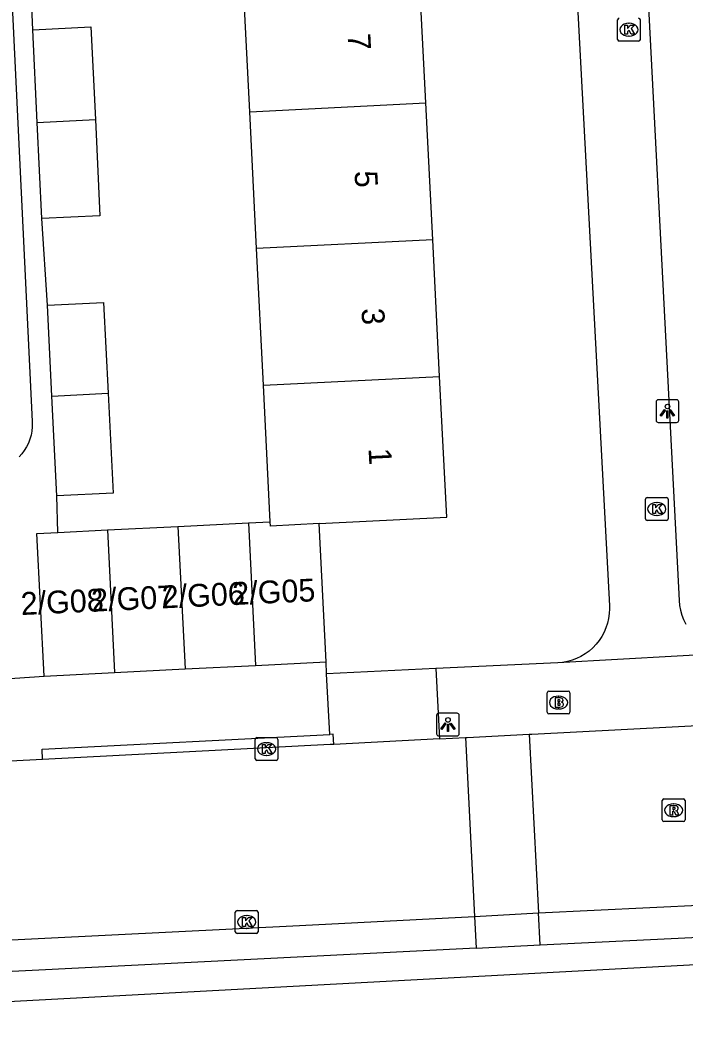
# Model space of a CAD drawing. Extents: x 161084 to 161928, y 385355 to 386522.
# Drawn here: x 161538.55 to 161567.76, y 385444.58 to 385488.38 of the extents above; entities that cross this region are included whole.
import ezdxf

# ---------------------------------------------------------------- set-up
doc = ezdxf.new("R2010")
doc.units = 0
for name, color, linetype in [('IMGEO_Brandkraan', 7, 'Continuous'), ('IMGEO_Kolk', 7, 'Continuous'), ('IMGEO_Lichtpunt', 7, 'Continuous'), ('IMGEO_Pand', 7, 'Continuous'), ('IMGEO_Pand_nummerreeks', 7, 'Continuous'), ('IMGEO_Parkeervlak_open', 7, 'Continuous'), ('IMGEO_Rijbaan_lokaal_open', 7, 'Continuous'), ('IMGEO_Rioolput', 7, 'Continuous'), ('IMGEO_Voetpad_open', 7, 'Continuous')]:
    doc.layers.add(name, color=color, linetype=linetype)

msp = doc.modelspace()

# ---------------------------------------------------------------- linework, layer by layer
at = {"layer": 'IMGEO_Brandkraan'}
for p, q in [((161561.702, 385457.968), (161561.702, 385458.82)), ((161561.777, 385458.894), (161562.629, 385458.894)), ((161562.703, 385458.82), (161562.703, 385457.968)), ((161562.19, 385458.674), (161562.215, 385458.674)), ((161562.629, 385457.894), (161561.777, 385457.894)), ((161562.213, 385458.114), (161562.188, 385458.114))]:
    msp.add_line(p, q, dxfattribs=at)
for points in [[(161561.702, 385457.968), (161561.702, 385458.82)], [(161561.777, 385458.894), (161562.629, 385458.894)], [(161562.703, 385458.82), (161562.703, 385457.968)], [(161562.05, 385458.594), (161562.05, 385458.194), (161562.263, 385458.194)], [(161562.281, 385458.594), (161562.05, 385458.594)], [(161562.229, 385458.513), (161562.175, 385458.513), (161562.175, 385458.437)], [(161562.175, 385458.437), (161562.228, 385458.437)], [(161562.237, 385458.361), (161562.175, 385458.361), (161562.175, 385458.28)], [(161562.175, 385458.28), (161562.237, 385458.28)], [(161562.629, 385457.894), (161561.777, 385457.894)]]:
    msp.add_lwpolyline(points, dxfattribs=at)
for centre, radius, start, end in [((161561.779, 385458.818), 0.0765, 91.552, 178.448), ((161561.779, 385458.818), 0.0765, 91.552, 178.448), ((161562.627, 385458.818), 0.0765, 1.552, 88.448), ((161562.627, 385458.818), 0.0765, 1.552, 88.448), ((161562.23, 385458.475), 0.0379, 267.8285, 90.9355), ((161562.238, 385458.32), 0.0404, 269.8759, 90.5077), ((161562.285, 385458.449), 0.145, 59.4692, 91.5367), ((161562.31, 385458.496), 0.0922, 285.5137, 58.1501), ((161562.315, 385458.304), 0.105, 301.3115, 78.989), ((161561.779, 385457.97), 0.0765, 181.552, 268.448), ((161561.779, 385457.97), 0.0765, 181.552, 268.448), ((161562.269, 385458.445), 0.251, 268.6676, 293.5347), ((161562.627, 385457.97), 0.0765, 271.552, 358.448), ((161562.627, 385457.97), 0.0765, 271.552, 358.448)]:
    msp.add_arc(centre, radius, start, end, dxfattribs=at)
for centre, major_axis, ratio, start_param, end_param in [((161562.189, 385458.394), (-0.387, 0.002), 0.722429, 4.712389, 7.853982), ((161562.214, 385458.394), (-0.39, 0.002), 0.717154, 1.570796, 4.712389)]:
    msp.add_ellipse(centre, major_axis=major_axis, ratio=ratio, start_param=start_param, end_param=end_param, dxfattribs=at)
at = {"layer": 'IMGEO_Kolk'}
for p, q in [((161564.792, 385487.526), (161564.792, 385488.378)), ((161565.28, 385488.232), (161565.305, 385488.232)), ((161565.793, 385488.378), (161565.793, 385487.526)), ((161565.303, 385487.672), (161565.278, 385487.672)), ((161565.719, 385487.452), (161564.867, 385487.452)), ((161566.015, 385466.468), (161566.015, 385467.32)), ((161566.09, 385467.394), (161566.942, 385467.394)), ((161566.503, 385467.174), (161566.528, 385467.174)), ((161567.016, 385467.32), (161567.016, 385466.468)), ((161566.526, 385466.614), (161566.501, 385466.614)), ((161566.942, 385466.394), (161566.09, 385466.394)), ((161548.876, 385455.925), (161548.876, 385456.777)), ((161548.951, 385456.851), (161549.803, 385456.851)), ((161549.364, 385456.631), (161549.389, 385456.631)), ((161549.877, 385456.777), (161549.877, 385455.925)), ((161549.803, 385455.851), (161548.951, 385455.851)), ((161549.387, 385456.071), (161549.362, 385456.071)), ((161548.005, 385448.328), (161548.005, 385449.18)), ((161548.08, 385449.254), (161548.932, 385449.254)), ((161549.006, 385449.18), (161549.006, 385448.328)), ((161548.493, 385449.034), (161548.518, 385449.034)), ((161548.932, 385448.254), (161548.08, 385448.254)), ((161548.516, 385448.474), (161548.491, 385448.474))]:
    msp.add_line(p, q, dxfattribs=at)
for points in [[(161564.792, 385487.526), (161564.792, 385488.378)], [(161565.113, 385488.152), (161565.236, 385488.152), (161565.236, 385488.001), (161565.366, 385488.152), (161565.53, 385488.152), (161565.384, 385488.001), (161565.537, 385487.752), (161565.385, 385487.752), (161565.3, 385487.916), (161565.236, 385487.849), (161565.236, 385487.752), (161565.113, 385487.752), (161565.113, 385488.152)], [(161565.793, 385488.378), (161565.793, 385487.526)], [(161565.719, 385487.452), (161564.867, 385487.452)], [(161566.015, 385466.468), (161566.015, 385467.32)], [(161566.09, 385467.394), (161566.942, 385467.394)], [(161566.336, 385467.094), (161566.459, 385467.094), (161566.459, 385466.943), (161566.589, 385467.094), (161566.753, 385467.094), (161566.607, 385466.943), (161566.76, 385466.694), (161566.608, 385466.694), (161566.523, 385466.858), (161566.459, 385466.791), (161566.459, 385466.694), (161566.336, 385466.694), (161566.336, 385467.094)], [(161567.016, 385467.32), (161567.016, 385466.468)], [(161566.942, 385466.394), (161566.09, 385466.394)], [(161548.876, 385455.925), (161548.876, 385456.777)], [(161548.951, 385456.851), (161549.803, 385456.851)], [(161549.197, 385456.551), (161549.32, 385456.551), (161549.32, 385456.4), (161549.45, 385456.551), (161549.614, 385456.551), (161549.468, 385456.4), (161549.621, 385456.151), (161549.469, 385456.151), (161549.384, 385456.315), (161549.32, 385456.248), (161549.32, 385456.151), (161549.197, 385456.151), (161549.197, 385456.551)], [(161549.877, 385456.777), (161549.877, 385455.925)], [(161549.803, 385455.851), (161548.951, 385455.851)], [(161548.005, 385448.328), (161548.005, 385449.18)], [(161548.08, 385449.254), (161548.932, 385449.254)], [(161549.006, 385449.18), (161549.006, 385448.328)], [(161548.326, 385448.954), (161548.449, 385448.954), (161548.449, 385448.803), (161548.579, 385448.954), (161548.743, 385448.954), (161548.597, 385448.803), (161548.75, 385448.554), (161548.598, 385448.554), (161548.513, 385448.718), (161548.449, 385448.651), (161548.449, 385448.554), (161548.326, 385448.554), (161548.326, 385448.954)], [(161548.932, 385448.254), (161548.08, 385448.254)]]:
    msp.add_lwpolyline(points, dxfattribs=at)
for centre, start, end in [((161564.869, 385488.376), 91.552, 178.448), ((161564.869, 385488.376), 91.552, 178.448), ((161565.717, 385488.376), 1.552, 88.448), ((161565.717, 385488.376), 1.552, 88.448), ((161564.869, 385487.528), 181.552, 268.448), ((161564.869, 385487.528), 181.552, 268.448), ((161565.717, 385487.528), 271.552, 358.448), ((161565.717, 385487.528), 271.552, 358.448), ((161566.092, 385467.318), 91.552, 178.448), ((161566.092, 385467.318), 91.552, 178.448), ((161566.94, 385467.318), 1.552, 88.448), ((161566.94, 385467.318), 1.552, 88.448), ((161566.092, 385466.47), 181.552, 268.448), ((161566.092, 385466.47), 181.552, 268.448), ((161566.94, 385466.47), 271.552, 358.448), ((161566.94, 385466.47), 271.552, 358.448), ((161548.953, 385456.775), 91.552, 178.448), ((161548.953, 385456.775), 91.552, 178.448), ((161549.801, 385456.775), 1.552, 88.448), ((161549.801, 385456.775), 1.552, 88.448), ((161548.953, 385455.927), 181.552, 268.448), ((161548.953, 385455.927), 181.552, 268.448), ((161549.801, 385455.927), 271.552, 358.448), ((161549.801, 385455.927), 271.552, 358.448), ((161548.082, 385449.178), 91.552, 178.448), ((161548.082, 385449.178), 91.552, 178.448), ((161548.93, 385449.178), 1.552, 88.448), ((161548.93, 385449.178), 1.552, 88.448), ((161548.082, 385448.33), 181.552, 268.448), ((161548.082, 385448.33), 181.552, 268.448), ((161548.93, 385448.33), 271.552, 358.448), ((161548.93, 385448.33), 271.552, 358.448)]:
    msp.add_arc(centre, 0.0765, start, end, dxfattribs=at)
for centre, major_axis, ratio, start_param, end_param in [((161565.279, 385487.952), (-0.387, 0.002), 0.722429, 4.712389, 7.853982), ((161565.304, 385487.952), (-0.39, 0.002), 0.717154, 1.570796, 4.712389), ((161566.502, 385466.894), (-0.387, 0.002), 0.722429, 4.712389, 7.853982), ((161566.527, 385466.894), (-0.39, 0.002), 0.717154, 1.570796, 4.712389), ((161549.363, 385456.351), (-0.387, 0.002), 0.722429, 4.712389, 7.853982), ((161549.388, 385456.351), (-0.39, 0.002), 0.717154, 1.570796, 4.712389), ((161548.492, 385448.754), (-0.387, 0.002), 0.722429, 4.712389, 7.853982), ((161548.517, 385448.754), (-0.39, 0.002), 0.717154, 1.570796, 4.712389)]:
    msp.add_ellipse(centre, major_axis=major_axis, ratio=ratio, start_param=start_param, end_param=end_param, dxfattribs=at)
at = {"layer": 'IMGEO_Lichtpunt'}
for p, q in [((161566.484, 385471.597), (161566.484, 385470.79)), ((161566.484, 385471.597), (161566.484, 385470.79)), ((161567.386, 385471.692), (161566.578, 385471.692)), ((161567.386, 385471.692), (161566.578, 385471.692)), ((161567.48, 385470.79), (161567.48, 385471.597)), ((161567.48, 385470.79), (161567.48, 385471.597)), ((161566.578, 385470.696), (161567.386, 385470.696)), ((161566.578, 385470.696), (161567.386, 385470.696)), ((161557.747, 385457.927), (161556.939, 385457.927)), ((161557.747, 385457.927), (161556.939, 385457.927)), ((161556.845, 385457.832), (161556.845, 385457.025)), ((161556.845, 385457.832), (161556.845, 385457.025)), ((161557.841, 385457.025), (161557.841, 385457.832)), ((161557.841, 385457.025), (161557.841, 385457.832)), ((161556.939, 385456.931), (161557.747, 385456.931)), ((161556.939, 385456.931), (161557.747, 385456.931))]:
    msp.add_line(p, q, dxfattribs=at)
for points in [[(161566.858, 385471.261), (161566.897, 385471.233), (161566.709, 385470.971), (161566.671, 385470.998), (161566.858, 385471.261)], [(161566.96, 385471.213), (161567.007, 385471.213), (161567.007, 385470.891), (161566.96, 385470.891), (161566.96, 385471.213)], [(161567.07, 385471.233), (161567.108, 385471.26), (161567.295, 385470.998), (161567.256, 385470.97), (161567.07, 385471.233)], [(161557.219, 385457.496), (161557.258, 385457.468), (161557.07, 385457.206), (161557.032, 385457.233), (161557.219, 385457.496)], [(161557.321, 385457.448), (161557.368, 385457.448), (161557.368, 385457.126), (161557.321, 385457.126), (161557.321, 385457.448)], [(161557.431, 385457.468), (161557.469, 385457.495), (161557.656, 385457.233), (161557.617, 385457.205), (161557.431, 385457.468)]]:
    msp.add_lwpolyline(points, dxfattribs=at)
for centre in [(161566.983, 385471.395), (161557.344, 385457.63)]:
    msp.add_circle(centre, 0.0994, dxfattribs=at)
for centre, start, end in [((161566.578, 385471.597), 90, 180), ((161566.578, 385471.597), 90, 180), ((161567.386, 385471.597), 0, 90), ((161567.386, 385471.597), 0, 90), ((161566.578, 385470.79), 180, 270), ((161566.578, 385470.79), 180, 270), ((161567.386, 385470.79), 270, 0), ((161567.386, 385470.79), 270, 360), ((161556.939, 385457.832), 90, 180), ((161556.939, 385457.832), 90, 180), ((161557.747, 385457.832), 0, 90), ((161557.747, 385457.832), 0, 90), ((161556.939, 385457.025), 180, 270), ((161556.939, 385457.025), 180, 270), ((161557.747, 385457.025), 270, 0), ((161557.747, 385457.025), 270, 360)]:
    msp.add_arc(centre, 0.0946, start, end, dxfattribs=at)
at = {"layer": 'IMGEO_Pand'}
for points in [[(161556.372, 385484.73), (161556.068, 385490.735)], [(161548.639, 385484.34), (161548.353, 385490.088)], [(161539.114, 385487.949), (161541.665, 385488.07), (161541.857, 385483.998)], [(161539.307, 385483.869), (161539.114, 385487.949)], [(161548.639, 385484.34), (161556.372, 385484.73)], [(161556.676, 385478.724), (161556.372, 385484.73)], [(161548.939, 385478.333), (161548.639, 385484.34)], [(161539.307, 385483.869), (161541.857, 385483.998)], [(161539.506, 385479.653), (161539.307, 385483.869)], [(161541.857, 385483.998), (161542.057, 385479.774), (161539.506, 385479.653)], [(161556.676, 385478.724), (161548.939, 385478.333)], [(161556.979, 385472.719), (161556.676, 385478.724)], [(161549.238, 385472.328), (161548.939, 385478.333)], [(161539.754, 385475.844), (161542.217, 385475.966), (161542.415, 385471.983)], [(161539.952, 385471.859), (161539.754, 385475.844)], [(161549.238, 385472.328), (161556.979, 385472.719)], [(161549.537, 385466.337), (161549.238, 385472.328)], [(161551.681, 385466.253), (161557.292, 385466.539), (161556.979, 385472.719)], [(161539.952, 385471.859), (161542.415, 385471.983)], [(161540.17, 385467.472), (161539.952, 385471.859)], [(161542.415, 385471.983), (161542.633, 385467.594), (161540.17, 385467.472)], [(161545.482, 385466.13), (161548.577, 385466.288)], [(161548.577, 385466.288), (161549.537, 385466.337)], [(161548.577, 385466.288), (161548.896, 385460.027)], [(161551.681, 385466.253), (161549.546, 385466.147), (161549.537, 385466.337)], [(161551.99, 385460.184), (161551.681, 385466.253)], [(161539.612, 385459.554), (161539.294, 385465.815), (161540.207, 385465.862)], [(161540.207, 385465.862), (161542.388, 385465.973)], [(161542.388, 385465.973), (161545.482, 385466.13)], [(161542.388, 385465.973), (161542.706, 385459.712)], [(161545.482, 385466.13), (161545.801, 385459.869)], [(161545.801, 385459.869), (161548.896, 385460.027)], [(161548.896, 385460.027), (161551.99, 385460.184)], [(161539.612, 385459.554), (161542.706, 385459.712)], [(161542.706, 385459.712), (161545.801, 385459.869)], [(161575.301, 385447.248), (161530.941, 385444.868), (161530.957, 385444.578)]]:
    msp.add_lwpolyline(points, dxfattribs=at)
at = {"layer": 'IMGEO_Parkeervlak_open'}
for points in [[(161561.395, 385447.744), (161561.322, 385449.16)], [(161558.515, 385448.993), (161558.586, 385447.605)]]:
    msp.add_lwpolyline(points, dxfattribs=at)
at = {"layer": 'IMGEO_Rijbaan_lokaal_open'}
for points in [[(161560.918, 385457), (161561.024, 385457.005), (161583.443, 385458.171)], [(161558.111, 385456.854), (161558.187, 385456.858), (161560.918, 385457)], [(161560.918, 385457), (161561.322, 385449.16)], [(161552.326, 385456.553), (161552.175, 385456.545), (161539.541, 385455.888)], [(161556.969, 385456.794), (161552.326, 385456.553)], [(161556.969, 385456.794), (161558.111, 385456.854)], [(161558.111, 385456.854), (161558.515, 385448.993)], [(161539.541, 385455.888), (161538.131, 385455.814)], [(161561.322, 385449.16), (161568.656, 385449.513), (161574.004, 385449.781)], [(161558.515, 385448.993), (161561.322, 385449.16)], [(161522.558, 385447.214), (161526.215, 385447.371), (161534.038, 385447.759), (161550.827, 385448.607), (161558.515, 385448.993)]]:
    msp.add_lwpolyline(points, dxfattribs=at)
at = {"layer": 'IMGEO_Rioolput'}
for p, q in [((161566.756, 385453.237), (161566.756, 385454.089)), ((161566.831, 385454.163), (161567.683, 385454.163)), ((161567.244, 385453.943), (161567.269, 385453.943)), ((161567.757, 385454.089), (161567.757, 385453.237)), ((161567.683, 385453.163), (161566.831, 385453.163)), ((161567.267, 385453.383), (161567.242, 385453.383))]:
    msp.add_line(p, q, dxfattribs=at)
for points in [[(161566.756, 385453.237), (161566.756, 385454.089)], [(161566.831, 385454.163), (161567.683, 385454.163)], [(161567.757, 385454.089), (161567.757, 385453.237)], [(161567.345, 385453.861), (161567.093, 385453.863), (161567.093, 385453.463)], [(161567.093, 385453.463), (161567.217, 385453.463), (161567.217, 385453.625), (161567.228, 385453.625)], [(161567.271, 385453.782), (161567.217, 385453.782), (161567.217, 385453.701)], [(161567.217, 385453.701), (161567.269, 385453.701)], [(161567.275, 385453.596), (161567.346, 385453.463), (161567.486, 385453.463), (161567.421, 385453.589)], [(161567.683, 385453.163), (161566.831, 385453.163)]]:
    msp.add_lwpolyline(points, dxfattribs=at)
for centre, radius, start, end in [((161566.833, 385454.087), 0.0765, 91.552, 178.448), ((161566.833, 385454.087), 0.0765, 91.552, 178.448), ((161567.681, 385454.087), 0.0765, 1.552, 88.448), ((161567.681, 385454.087), 0.0765, 1.552, 88.448), ((161567.227, 385453.572), 0.0533, 26.0293, 88.6989), ((161567.253, 385453.89), 0.19, 274.7715, 282.9687), ((161567.277, 385453.686), 0.0964, 77.0061, 93.1865), ((161567.291, 385453.743), 0.0378, 276.6634, 79.6772), ((161567.344, 385453.751), 0.109, 350.3612, 89.416), ((161567.342, 385453.751), 0.112, 277.5842, 350.9817), ((161567.326, 385453.536), 0.108, 29.5134, 73.7905), ((161566.833, 385453.239), 0.0765, 181.552, 268.448), ((161566.833, 385453.239), 0.0765, 181.552, 268.448), ((161567.681, 385453.239), 0.0765, 271.552, 358.448), ((161567.681, 385453.239), 0.0765, 271.552, 358.448)]:
    msp.add_arc(centre, radius, start, end, dxfattribs=at)
for centre, major_axis, ratio, start_param, end_param in [((161567.243, 385453.663), (-0.387, 0.002), 0.722429, 4.712389, 7.853982), ((161567.268, 385453.663), (-0.39, 0.002), 0.717154, 1.570796, 4.712389)]:
    msp.add_ellipse(centre, major_axis=major_axis, ratio=ratio, start_param=start_param, end_param=end_param, dxfattribs=at)
at = {"layer": 'IMGEO_Voetpad_open'}
for points in [[(161560.807, 385530.642), (161560.832, 385530.373), (161562.447, 385500), (161564.433, 385462.644), (161564.436, 385462.514), (161564.426, 385462.301), (161564.397, 385462.09), (161564.349, 385461.882), (161564.283, 385461.68), (161564.199, 385461.484), (161564.098, 385461.296), (161563.981, 385461.118), (161563.848, 385460.951), (161563.701, 385460.797), (161563.54, 385460.657), (161563.368, 385460.531), (161563.185, 385460.422), (161562.993, 385460.329), (161562.793, 385460.254), (161562.588, 385460.196), (161562.378, 385460.158), (161562.166, 385460.138)], [(161537.657, 385500), (161539.087, 385470.737), (161539.089, 385470.687), (161539.087, 385470.503), (161539.068, 385470.32), (161539.033, 385470.14), (161538.981, 385469.964), (161538.915, 385469.793), (161538.833, 385469.628), (161538.737, 385469.472), (161538.627, 385469.324), (161538.505, 385469.187)], [(161565.576, 385500), (161567.496, 385462.875), (161567.517, 385462.659), (161567.557, 385462.446), (161567.617, 385462.237), (161567.694, 385462.035), (161567.789, 385461.84)], [(161539.114, 385487.949), (161538.947, 385491.627)], [(161539.754, 385475.844), (161539.506, 385479.653)], [(161540.207, 385465.862), (161540.17, 385467.472)], [(161570.036, 385460.58), (161562.166, 385460.138)], [(161552.017, 385459.658), (161551.99, 385460.184)], [(161562.166, 385460.138), (161556.811, 385459.885)], [(161556.811, 385459.885), (161552.017, 385459.658)], [(161552.152, 385456.995), (161552.017, 385459.658)], [(161556.811, 385459.885), (161556.969, 385456.794)], [(161537.678, 385459.424), (161539.612, 385459.554)], [(161539.541, 385455.888), (161539.516, 385456.345), (161552.152, 385456.995)], [(161552.326, 385456.553), (161552.302, 385457.003), (161552.152, 385456.995)], [(161561.395, 385447.744), (161568.97, 385448.12), (161571.983, 385448.231)], [(161558.586, 385447.605), (161533.828, 385446.361), (161525.327, 385445.893)], [(161558.586, 385447.605), (161561.395, 385447.744)]]:
    msp.add_lwpolyline(points, dxfattribs=at)

# ---------------------------------------------------------------- texts
at = {"layer": 'IMGEO_Pand_nummerreeks'}
for s, rotation, p in [('7', 272.8932, (161552.934, 385487.77)), ('5', 272.8949, (161553.239, 385481.735)), ('3', 272.8949, (161553.544, 385475.7)), ('1', 272.8949, (161553.855, 385469.552)), ('2/G07', 2.7102, (161541.702, 385462.382)), ('2/G06', 2.7102, (161544.801, 385462.528)), ('2/G05', 2.7102, (161547.9, 385462.675)), ('2/G08', 2.7102, (161538.606, 385462.235))]:
    msp.add_text(s, height=1, rotation=rotation, dxfattribs=at).set_placement(p)

doc.saveas('drawing.dxf')
